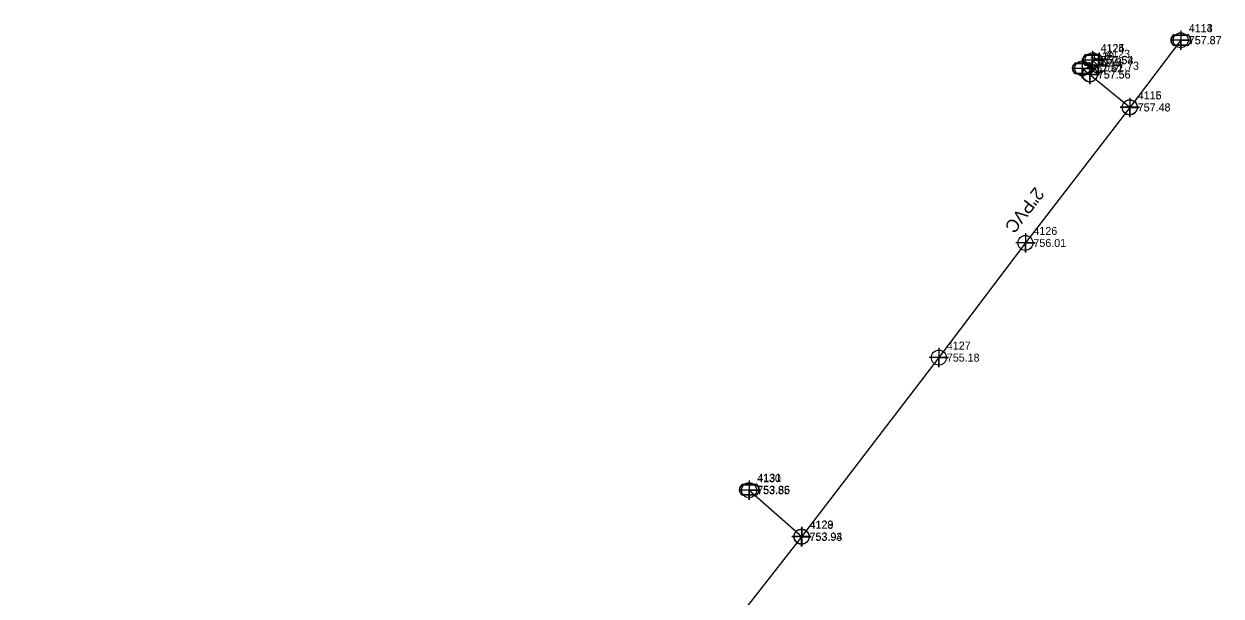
# Model space of a CAD drawing. Extents: x 1622486 to 1624761, y 758733 to 760816.
# Drawn here: x 1622488.7 to 1622862.6, y 759180.5 to 759359.1 of the extents above; entities that cross this region are included whole.
import ezdxf

# ---------------------------------------------------------------- set-up
doc = ezdxf.new("R2010")
doc.units = 0
for name, color, linetype in [('Exist Structure Minor Catch Basin Top Elevation', 7, 'Continuous'), ('Exist Utilities Water Meter CELL', 7, 'Continuous'), ('Exist Utilities Water Meter Cogo Elevation', 7, 'Continuous'), ('Exist Utilities Water Meter Cogo Number', 7, 'Continuous'), ('Exist Utilities Water UG Line SUE', 7, 'Continuous'), ('Exist Utilities Water UG Line SUE Cogo Elevation', 7, 'Continuous'), ('Exist Utilities Water UG Line SUE Cogo Number', 7, 'Continuous'), ('Exist Utilities Water UG Line SUE Cogo Point CELL', 7, 'Continuous')]:
    doc.layers.add(name, color=color, linetype=linetype)

msp = doc.modelspace()

# ---------------------------------------------------------------- linework, layer by layer
at = {"layer": 'Exist Utilities Water Meter CELL'}
for p, q in [((1622850.07, 759354.01), (1622850.07, 759354.01)), ((1622819.3, 759345.2), (1622819.3, 759345.2)), ((1622822.51, 759347.77), (1622822.51, 759347.77)), ((1622715.28, 759213.68), (1622715.28, 759213.68))]:
    msp.add_line(p, q, dxfattribs=at)
for points in [[(1622852.1, 759352.45), (1622848, 759352.45)], [(1622852.1, 759352.31), (1622848, 759352.31)], [(1622848.03, 759355.71), (1622852.1, 759355.71)], [(1622848.03, 759355.58), (1622852.1, 759355.58)], [(1622820.47, 759349.47), (1622824.55, 759349.47)], [(1622820.47, 759349.33), (1622824.55, 759349.33)], [(1622817.26, 759346.9), (1622821.33, 759346.9)], [(1622817.26, 759346.76), (1622821.33, 759346.76)], [(1622824.55, 759346.21), (1622820.45, 759346.21)], [(1622824.55, 759346.07), (1622820.45, 759346.07)], [(1622821.33, 759343.63), (1622817.23, 759343.63)], [(1622821.33, 759343.5), (1622817.23, 759343.5)], [(1622713.25, 759215.38), (1622717.32, 759215.38)], [(1622713.25, 759215.24), (1622717.32, 759215.24)], [(1622717.32, 759212.12), (1622713.22, 759212.12)], [(1622717.32, 759211.98), (1622713.22, 759211.98)]]:
    msp.add_lwpolyline(points, dxfattribs=at)
for centre, radius, start, end in [((1622848.76, 759354.01), 1.86, 113.178, 245.9794), ((1622848.77, 759354.01), 1.73, 115.3009, 243.7824), ((1622851.36, 759354.02), 1.86, 293.6483, 66.3084), ((1622851.37, 759354.01), 1.73, 295.1272, 64.8728), ((1622821.2, 759347.77), 1.86, 113.178, 245.9794), ((1622821.21, 759347.76), 1.73, 115.3009, 243.7824), ((1622823.8, 759347.77), 1.86, 293.6483, 66.3084), ((1622823.81, 759347.77), 1.73, 295.1272, 64.8728), ((1622817.99, 759345.19), 1.86, 113.178, 245.9794), ((1622818, 759345.19), 1.73, 115.3009, 243.7824), ((1622820.59, 759345.2), 1.86, 293.6483, 66.3084), ((1622820.6, 759345.2), 1.73, 295.1272, 64.8728), ((1622713.98, 759213.67), 1.86, 113.178, 245.9794), ((1622713.99, 759213.67), 1.73, 115.3009, 243.7824), ((1622716.58, 759213.68), 1.86, 293.6483, 66.3084), ((1622716.59, 759213.68), 1.73, 295.1272, 64.8728)]:
    msp.add_arc(centre, radius, start, end, dxfattribs=at)
at = {"layer": 'Exist Utilities Water UG Line SUE'}
msp.add_line((1622715.19, 759213.53), (1622731.62, 759199.07), dxfattribs=at)
for points in [[(1622850.03, 759353.96), (1622834.08, 759332.99), (1622801.51, 759290.71), (1622774.47, 759254.92), (1622731.55, 759198.97), (1622709.07, 759170.23), (1622677.31, 759129.28), (1622642.64, 759084.03), (1622615.18, 759048.72), (1622576.79, 758998.29), (1622538.1, 758947.15), (1622513.42, 758915.16), (1622488.68, 758882.67)], [(1622819.28, 759345.18), (1622821.61, 759343.24), (1622834.12, 759333.04)], [(1622821.66, 759343.32), (1622824.25, 759346.01), (1622822.47, 759347.71)]]:
    msp.add_lwpolyline(points, dxfattribs=at)
at = {"layer": 'Exist Utilities Water UG Line SUE Cogo Point CELL'}
for points in [[(1622850.03, 759356.96), (1622850.03, 759350.96), (1622850.03, 759353.96), (1622853.03, 759353.96), (1622847.03, 759353.96)], [(1622822.47, 759350.71), (1622822.47, 759344.71), (1622822.47, 759347.71), (1622825.47, 759347.71), (1622819.47, 759347.71)], [(1622824.25, 759349.01), (1622824.25, 759343.01), (1622824.25, 759346.01), (1622827.25, 759346.01), (1622821.25, 759346.01)], [(1622819.28, 759348.18), (1622819.28, 759342.18), (1622819.28, 759345.18), (1622822.28, 759345.18), (1622816.28, 759345.18)], [(1622821.61, 759346.24), (1622821.61, 759340.24), (1622821.61, 759343.24), (1622824.61, 759343.24), (1622818.61, 759343.24)], [(1622821.66, 759346.32), (1622821.66, 759340.32), (1622821.66, 759343.32), (1622824.66, 759343.32), (1622818.66, 759343.32)], [(1622834.08, 759335.99), (1622834.08, 759329.99), (1622834.08, 759332.99), (1622837.08, 759332.99), (1622831.08, 759332.99)], [(1622834.12, 759336.04), (1622834.12, 759330.04), (1622834.12, 759333.04), (1622837.12, 759333.04), (1622831.12, 759333.04)], [(1622801.51, 759293.71), (1622801.51, 759287.71), (1622801.51, 759290.71), (1622804.51, 759290.71), (1622798.51, 759290.71)], [(1622774.47, 759257.92), (1622774.47, 759251.92), (1622774.47, 759254.92), (1622777.47, 759254.92), (1622771.47, 759254.92)], [(1622715.19, 759216.53), (1622715.19, 759210.53), (1622715.19, 759213.53), (1622718.19, 759213.53), (1622712.19, 759213.53)], [(1622731.55, 759201.97), (1622731.55, 759195.97), (1622731.55, 759198.97), (1622734.55, 759198.97), (1622728.55, 759198.97)], [(1622731.62, 759202.07), (1622731.62, 759196.07), (1622731.62, 759199.07), (1622734.62, 759199.07), (1622728.62, 759199.07)]]:
    msp.add_lwpolyline(points, dxfattribs=at)
for centre in [(1622850.03, 759353.96), (1622822.47, 759347.71), (1622819.28, 759345.18), (1622821.61, 759343.24), (1622821.66, 759343.32), (1622824.25, 759346.01), (1622834.08, 759332.99), (1622834.12, 759333.04), (1622801.51, 759290.71), (1622774.47, 759254.92), (1622715.19, 759213.53), (1622731.55, 759198.97), (1622731.62, 759199.07)]:
    msp.add_circle(centre, 2.34, dxfattribs=at)

# ---------------------------------------------------------------- texts
at = {"layer": 'Exist Structure Minor Catch Basin Top Elevation'}
msp.add_text('2"PVC', height=4, rotation=232.3861, dxfattribs=at).set_placement((1622804.54, 759308.42))
at = {"layer": 'Exist Utilities Water Meter Cogo Elevation'}
for s, p in [('757.87', (1622852.57, 759352.76)), ('757.54', (1622825.01, 759346.52)), ('757.61', (1622821.8, 759343.95)), ('753.86', (1622717.78, 759212.43))]:
    msp.add_text(s, height=2.5, dxfattribs=at).set_placement(p)
at = {"layer": 'Exist Utilities Water Meter Cogo Number'}
for s, p in [('4113', (1622852.57, 759356.51)), ('4125', (1622825.01, 759350.27)), ('4120', (1622821.8, 759347.7)), ('4131', (1622717.78, 759216.18))]:
    msp.add_text(s, height=2.5, dxfattribs=at).set_placement(p)
at = {"layer": 'Exist Utilities Water UG Line SUE Cogo Elevation'}
for s, p in [('757.87', (1622852.53, 759352.71)), ('757.53', (1622824.97, 759346.46)), ('757.62', (1622821.78, 759343.93)), ('757.73', (1622826.75, 759344.76)), ('757.56', (1622824.11, 759341.99)), ('757.55', (1622824.16, 759342.07)), ('757.48', (1622836.58, 759331.74)), ('757.48', (1622836.62, 759331.79)), ('756.01', (1622804.01, 759289.46)), ('755.18', (1622776.97, 759253.67)), ('753.85', (1622717.69, 759212.28)), ('753.93', (1622734.05, 759197.72)), ('753.94', (1622734.12, 759197.82))]:
    msp.add_text(s, height=2.5, dxfattribs=at).set_placement(p)
at = {"layer": 'Exist Utilities Water UG Line SUE Cogo Number'}
for s, p in [('4114', (1622852.53, 759356.46)), ('4124', (1622824.97, 759350.21)), ('4119', (1622821.78, 759347.68)), ('4123', (1622826.75, 759348.51)), ('4117', (1622824.11, 759345.74)), ('4118', (1622824.16, 759345.82)), ('4115', (1622836.58, 759335.49)), ('4116', (1622836.62, 759335.54)), ('4126', (1622804.01, 759293.21)), ('4127', (1622776.97, 759257.42)), ('4130', (1622717.69, 759216.03)), ('4128', (1622734.05, 759201.47)), ('4129', (1622734.12, 759201.57))]:
    msp.add_text(s, height=2.5, dxfattribs=at).set_placement(p)

doc.saveas('drawing.dxf')
